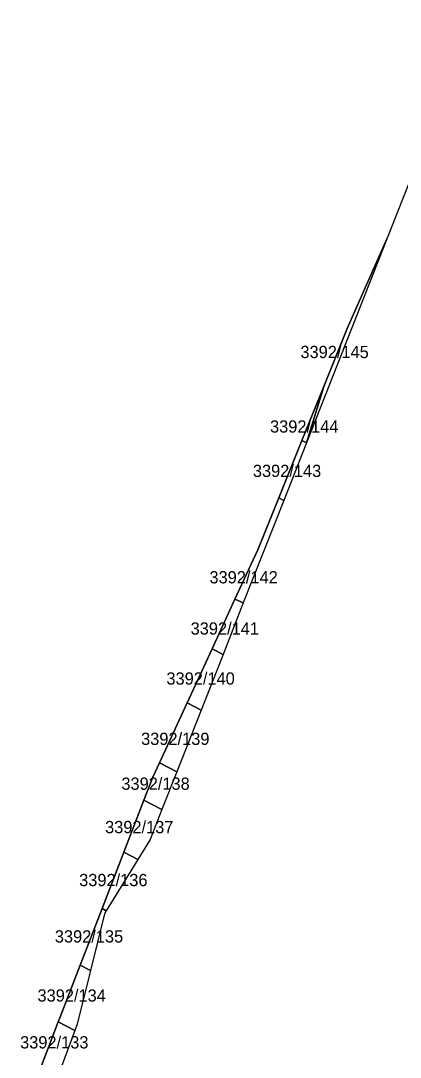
# Model space of a CAD drawing. Extents: x -262715 to -259381, y -1237238 to -1231182.
# Drawn here: x -261321.8 to -261259.8, y -1236357.8 to -1236188.7 of the extents above; entities that cross this region are included whole.
import ezdxf

# ---------------------------------------------------------------- set-up
doc = ezdxf.new("R2010")
doc.units = 0
for name, color, linetype in [('body_kn', 7, 'Continuous'), ('katuz_linie', 7, 'Continuous'), ('kladpar_druhypozemkov', 7, 'Continuous'), ('kladpar_hranice', 7, 'Continuous'), ('kladpar_parcelnecisla', 7, 'Continuous'), ('kladpar_plochy', 7, 'Continuous'), ('zuob_linie', 7, 'Continuous'), ('zuob_plochy', 7, 'Continuous')]:
    doc.layers.add(name, color=color, linetype=linetype)

msp = doc.modelspace()

# ---------------------------------------------------------------- linework, layer by layer
at = {"layer": 'body_kn'}
for p, q in [((-261261.98, -1236224.19), (-261261.98, -1236224.19)), ((-261268.49, -1236238.95), (-261268.49, -1236238.95)), ((-261272.32, -1236248.39), (-261272.32, -1236248.39)), ((-261272.32, -1236248.39), (-261272.32, -1236248.39)), ((-261275.89, -1236257.22), (-261275.89, -1236257.22)), ((-261275.89, -1236257.22), (-261275.89, -1236257.22)), ((-261275.16, -1236257.61), (-261275.16, -1236257.61)), ((-261275.16, -1236257.61), (-261275.16, -1236257.61)), ((-261279.68, -1236266.57), (-261279.68, -1236266.57)), ((-261279.68, -1236266.57), (-261279.68, -1236266.57)), ((-261278.86, -1236266.99), (-261278.86, -1236266.99)), ((-261278.86, -1236266.99), (-261278.86, -1236266.99)), ((-261283.1, -1236275.02), (-261283.1, -1236275.02)), ((-261286.81, -1236283.07), (-261286.81, -1236283.07)), ((-261286.81, -1236283.07), (-261286.81, -1236283.07)), ((-261285.45, -1236283.71), (-261285.45, -1236283.71)), ((-261285.45, -1236283.71), (-261285.45, -1236283.71)), ((-261290.56, -1236291.22), (-261290.56, -1236291.22)), ((-261290.56, -1236291.22), (-261290.56, -1236291.22)), ((-261288.76, -1236292.1), (-261288.76, -1236292.1)), ((-261288.76, -1236292.1), (-261288.76, -1236292.1)), ((-261294.62, -1236300.03), (-261294.62, -1236300.03)), ((-261294.62, -1236300.03), (-261294.62, -1236300.03)), ((-261292.34, -1236301.19), (-261292.34, -1236301.19)), ((-261292.34, -1236301.19), (-261292.34, -1236301.19)), ((-261299.12, -1236309.8), (-261299.12, -1236309.8)), ((-261299.12, -1236309.8), (-261299.12, -1236309.8)), ((-261300.21, -1236312.16), (-261300.21, -1236312.16)), ((-261296.31, -1236311.25), (-261296.31, -1236311.25)), ((-261296.31, -1236311.25), (-261296.31, -1236311.25)), ((-261301.66, -1236315.91), (-261301.66, -1236315.91)), ((-261301.66, -1236315.91), (-261301.66, -1236315.91)), ((-261298.74, -1236317.43), (-261298.74, -1236317.43)), ((-261298.74, -1236317.43), (-261298.74, -1236317.43)), ((-261300.66, -1236322.3), (-261300.66, -1236322.3)), ((-261300.66, -1236322.3), (-261300.66, -1236322.3)), ((-261304.95, -1236324.39), (-261304.95, -1236324.39)), ((-261304.95, -1236324.39), (-261304.95, -1236324.39)), ((-261302.68, -1236325.58), (-261302.68, -1236325.58)), ((-261302.68, -1236325.58), (-261302.68, -1236325.58)), ((-261308.5, -1236333.57), (-261308.5, -1236333.57)), ((-261308.5, -1236333.57), (-261308.5, -1236333.57)), ((-261307.82, -1236333.93), (-261307.82, -1236333.93)), ((-261307.82, -1236333.93), (-261307.82, -1236333.93)), ((-261308.11, -1236334.41), (-261308.11, -1236334.41)), ((-261312.08, -1236342.8), (-261312.08, -1236342.8)), ((-261312.08, -1236342.8), (-261312.08, -1236342.8)), ((-261310.51, -1236344.14), (-261310.51, -1236344.14)), ((-261310.4, -1236343.68), (-261310.4, -1236343.68)), ((-261310.4, -1236343.68), (-261310.4, -1236343.68)), ((-261315.66, -1236352.05), (-261315.66, -1236352.05)), ((-261315.66, -1236352.05), (-261315.66, -1236352.05)), ((-261315.42, -1236351.42), (-261315.42, -1236351.42)), ((-261312.56, -1236352.43), (-261312.56, -1236352.43)), ((-261312.56, -1236352.43), (-261312.56, -1236352.43)), ((-261312.95, -1236353.48), (-261312.95, -1236353.48)), ((-261312.95, -1236353.48), (-261312.95, -1236353.48))]:
    msp.add_line(p, q, dxfattribs=at)
at = {"layer": 'katuz_linie'}
msp.add_lwpolyline([(-261257.69, -1236213.3), (-261261.98, -1236224.19), (-261275.16, -1236257.61), (-261278.86, -1236266.99), (-261285.45, -1236283.71), (-261288.76, -1236292.1), (-261292.34, -1236301.19), (-261296.31, -1236311.25), (-261298.74, -1236317.43), (-261300.66, -1236322.3), (-261302.68, -1236325.58), (-261307.82, -1236333.93), (-261308.11, -1236334.41), (-261310.4, -1236343.68), (-261310.51, -1236344.14), (-261312.56, -1236352.43), (-261312.95, -1236353.48), (-261315.69, -1236360.83)], dxfattribs=at)
at = {"layer": 'kladpar_druhypozemkov'}
for p, q in [((-261269.09, -1236241.34), (-261269.09, -1236241.34)), ((-261274.64, -1236254.82), (-261274.64, -1236254.82)), ((-261277.03, -1236261.14), (-261277.03, -1236261.14)), ((-261283.68, -1236277.82), (-261283.68, -1236277.82)), ((-261287.56, -1236286.62), (-261287.56, -1236286.62)), ((-261290.68, -1236294.3), (-261290.68, -1236294.3)), ((-261295.05, -1236304.54), (-261295.05, -1236304.54)), ((-261298.39, -1236312.74), (-261298.39, -1236312.74)), ((-261301.32, -1236319.26), (-261301.32, -1236319.26)), ((-261305.08, -1236327.54), (-261305.08, -1236327.54)), ((-261309.49, -1236337.42), (-261309.49, -1236337.42)), ((-261312.49, -1236346.98), (-261312.49, -1236346.98)), ((-261315.3, -1236354.62), (-261315.3, -1236354.62))]:
    msp.add_line(p, q, dxfattribs=at)
at = {"layer": 'kladpar_hranice'}
for p, q in [((-261275.89, -1236257.22), (-261272.32, -1236248.39)), ((-261272.32, -1236248.39), (-261275.16, -1236257.61)), ((-261275.16, -1236257.61), (-261272.32, -1236248.39)), ((-261279.68, -1236266.57), (-261275.89, -1236257.22)), ((-261275.16, -1236257.61), (-261278.86, -1236266.99)), ((-261275.89, -1236257.22), (-261275.16, -1236257.61)), ((-261275.16, -1236257.61), (-261275.89, -1236257.22)), ((-261278.86, -1236266.99), (-261285.45, -1236283.71)), ((-261279.68, -1236266.57), (-261278.86, -1236266.99)), ((-261278.86, -1236266.99), (-261279.68, -1236266.57)), ((-261290.56, -1236291.22), (-261286.81, -1236283.07)), ((-261286.81, -1236283.07), (-261285.45, -1236283.71)), ((-261285.45, -1236283.71), (-261286.81, -1236283.07)), ((-261285.45, -1236283.71), (-261288.76, -1236292.1)), ((-261294.62, -1236300.03), (-261290.56, -1236291.22)), ((-261290.56, -1236291.22), (-261288.76, -1236292.1)), ((-261288.76, -1236292.1), (-261290.56, -1236291.22)), ((-261288.76, -1236292.1), (-261292.34, -1236301.19)), ((-261299.12, -1236309.8), (-261294.62, -1236300.03)), ((-261294.62, -1236300.03), (-261292.34, -1236301.19)), ((-261292.34, -1236301.19), (-261294.62, -1236300.03)), ((-261292.34, -1236301.19), (-261296.31, -1236311.25)), ((-261299.12, -1236309.8), (-261296.31, -1236311.25)), ((-261296.31, -1236311.25), (-261299.12, -1236309.8)), ((-261296.31, -1236311.25), (-261298.74, -1236317.43)), ((-261304.95, -1236324.39), (-261301.66, -1236315.91)), ((-261298.74, -1236317.43), (-261301.66, -1236315.91)), ((-261301.66, -1236315.91), (-261298.74, -1236317.43)), ((-261298.74, -1236317.43), (-261300.66, -1236322.3)), ((-261300.66, -1236322.3), (-261302.68, -1236325.58)), ((-261308.5, -1236333.57), (-261304.95, -1236324.39)), ((-261302.68, -1236325.58), (-261307.82, -1236333.93)), ((-261304.95, -1236324.39), (-261302.68, -1236325.58)), ((-261302.68, -1236325.58), (-261304.95, -1236324.39)), ((-261312.08, -1236342.8), (-261308.5, -1236333.57)), ((-261308.5, -1236333.57), (-261307.82, -1236333.93)), ((-261307.82, -1236333.93), (-261308.5, -1236333.57)), ((-261312.08, -1236342.8), (-261310.4, -1236343.68)), ((-261310.4, -1236343.68), (-261312.08, -1236342.8)), ((-261318.44, -1236359.35), (-261315.66, -1236352.05)), ((-261315.66, -1236352.05), (-261312.95, -1236353.48)), ((-261312.95, -1236353.48), (-261315.66, -1236352.05)), ((-261312.56, -1236352.43), (-261312.95, -1236353.48)), ((-261312.95, -1236353.48), (-261315.69, -1236360.83))]:
    msp.add_line(p, q, dxfattribs=at)
for points in [[(-261190.69, -1236053.68), (-261194.86, -1236063.16), (-261207.74, -1236092.4), (-261219.5, -1236124.41), (-261225.77, -1236137.59), (-261257.69, -1236213.3), (-261261.98, -1236224.19), (-261268.49, -1236238.95), (-261272.32, -1236248.39), (-261275.89, -1236257.22), (-261279.68, -1236266.57), (-261283.1, -1236275.02), (-261286.81, -1236283.07), (-261290.56, -1236291.22), (-261294.62, -1236300.03), (-261299.12, -1236309.8), (-261300.21, -1236312.16), (-261301.66, -1236315.91), (-261304.95, -1236324.39), (-261308.5, -1236333.57), (-261312.08, -1236342.8), (-261315.42, -1236351.42), (-261315.66, -1236352.05), (-261318.44, -1236359.35)], [(-261272.32, -1236248.39), (-261268.49, -1236238.95), (-261261.98, -1236224.19), (-261275.16, -1236257.61)], [(-261286.81, -1236283.07), (-261283.1, -1236275.02), (-261279.68, -1236266.57)], [(-261301.66, -1236315.91), (-261300.21, -1236312.16), (-261299.12, -1236309.8)], [(-261307.82, -1236333.93), (-261308.11, -1236334.41), (-261310.4, -1236343.68)], [(-261315.66, -1236352.05), (-261315.42, -1236351.42), (-261312.08, -1236342.8)], [(-261310.4, -1236343.68), (-261310.51, -1236344.14), (-261312.56, -1236352.43)]]:
    msp.add_lwpolyline(points, dxfattribs=at)
at = {"layer": 'kladpar_plochy'}
msp.add_lwpolyline([(-261257.69, -1236213.3), (-261261.98, -1236224.19), (-261268.49, -1236238.95), (-261272.32, -1236248.39), (-261275.89, -1236257.22), (-261279.68, -1236266.57), (-261283.1, -1236275.02), (-261286.81, -1236283.07), (-261290.56, -1236291.22), (-261294.62, -1236300.03), (-261299.12, -1236309.8), (-261300.21, -1236312.16), (-261301.66, -1236315.91), (-261304.95, -1236324.39), (-261308.5, -1236333.57), (-261312.08, -1236342.8), (-261315.42, -1236351.42), (-261315.66, -1236352.05), (-261318.44, -1236359.35)], dxfattribs=at)
for points in [[(-261272.32, -1236248.39), (-261268.49, -1236238.95), (-261261.98, -1236224.19), (-261275.16, -1236257.61)], [(-261275.89, -1236257.22), (-261272.32, -1236248.39), (-261275.16, -1236257.61)], [(-261279.68, -1236266.57), (-261275.89, -1236257.22), (-261275.16, -1236257.61), (-261278.86, -1236266.99)], [(-261286.81, -1236283.07), (-261283.1, -1236275.02), (-261279.68, -1236266.57), (-261278.86, -1236266.99), (-261285.45, -1236283.71)], [(-261290.56, -1236291.22), (-261286.81, -1236283.07), (-261285.45, -1236283.71), (-261288.76, -1236292.1)], [(-261294.62, -1236300.03), (-261290.56, -1236291.22), (-261288.76, -1236292.1), (-261292.34, -1236301.19)], [(-261299.12, -1236309.8), (-261294.62, -1236300.03), (-261292.34, -1236301.19), (-261296.31, -1236311.25)], [(-261301.66, -1236315.91), (-261300.21, -1236312.16), (-261299.12, -1236309.8), (-261296.31, -1236311.25), (-261298.74, -1236317.43)], [(-261300.66, -1236322.3), (-261302.68, -1236325.58), (-261304.95, -1236324.39), (-261301.66, -1236315.91), (-261298.74, -1236317.43)], [(-261308.5, -1236333.57), (-261304.95, -1236324.39), (-261302.68, -1236325.58), (-261307.82, -1236333.93)], [(-261312.08, -1236342.8), (-261308.5, -1236333.57), (-261307.82, -1236333.93), (-261308.11, -1236334.41), (-261310.4, -1236343.68)], [(-261312.56, -1236352.43), (-261312.95, -1236353.48), (-261315.66, -1236352.05), (-261315.42, -1236351.42), (-261312.08, -1236342.8), (-261310.4, -1236343.68), (-261310.51, -1236344.14)], [(-261315.66, -1236352.05), (-261312.95, -1236353.48), (-261315.69, -1236360.83), (-261318.44, -1236359.35)]]:
    msp.add_lwpolyline(points, close=True, dxfattribs=at)
at = {"layer": 'zuob_linie'}
msp.add_lwpolyline([(-261257.69, -1236213.3), (-261261.98, -1236224.19), (-261275.16, -1236257.61), (-261278.86, -1236266.99), (-261285.45, -1236283.71), (-261288.76, -1236292.1), (-261292.34, -1236301.19), (-261296.31, -1236311.25), (-261298.74, -1236317.43), (-261300.66, -1236322.3), (-261302.68, -1236325.58), (-261307.82, -1236333.93), (-261308.11, -1236334.41), (-261310.4, -1236343.68), (-261310.51, -1236344.14), (-261312.56, -1236352.43), (-261312.95, -1236353.48), (-261315.69, -1236360.83)], dxfattribs=at)
at = {"layer": 'zuob_plochy'}
msp.add_lwpolyline([(-261257.69, -1236213.3), (-261261.98, -1236224.19), (-261275.16, -1236257.61), (-261278.86, -1236266.99), (-261285.45, -1236283.71), (-261288.76, -1236292.1), (-261292.34, -1236301.19), (-261296.31, -1236311.25), (-261298.74, -1236317.43), (-261300.66, -1236322.3), (-261302.68, -1236325.58), (-261307.82, -1236333.93), (-261308.11, -1236334.41), (-261310.4, -1236343.68), (-261310.51, -1236344.14), (-261312.56, -1236352.43), (-261312.95, -1236353.48), (-261315.69, -1236360.83)], dxfattribs=at)

# ---------------------------------------------------------------- texts
at = {"layer": 'kladpar_parcelnecisla'}
for s, p in [('3392/145', (-261276.13, -1236243.76)), ('3392/144', (-261281.09, -1236255.92)), ('3392/143', (-261283.89, -1236263.16)), ('3392/142', (-261290.98, -1236280.52)), ('3392/141', (-261294.05, -1236288.88)), ('3392/140', (-261298, -1236297.04)), ('3392/139', (-261302.13, -1236306.88)), ('3392/138', (-261305.35, -1236314.2)), ('3392/137', (-261308.01, -1236321.28)), ('3392/136', (-261312.24, -1236329.92)), ('3392/135', (-261316.21, -1236339.12)), ('3392/134', (-261319.04, -1236348.76)), ('3392/133', (-261321.88, -1236356.4))]:
    msp.add_text(s, height=2, dxfattribs=at).set_placement(p)

doc.saveas('drawing.dxf')
